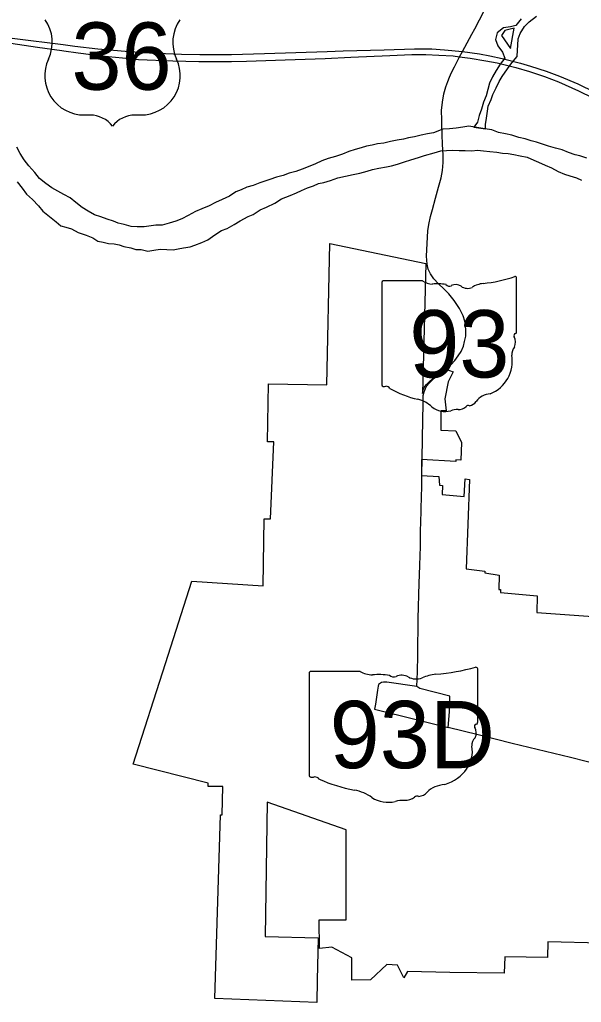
# Model space of a CAD drawing. Extents: x -6.3 to 34, y 0 to 22.
# Drawn here: x 10.181 to 10.934, y 11.977 to 13.296 of the extents above; entities that cross this region are included whole.
import ezdxf

# ---------------------------------------------------------------- set-up
doc = ezdxf.new("R2010")
doc.units = 0
for name, color, linetype in [('GM_X_Corporation', 7, 'Continuous'), ('GM_X_Major_River', 7, 'Continuous'), ('GM_X_Minor_Lake', 7, 'Continuous'), ('GM_X_Minor_River', 7, 'Continuous'), ('GM_X_State_Route', 7, 'Continuous'), ('GM_X_State_Shield', 7, 'Continuous'), ('GM_X_US_Location', 7, 'Continuous'), ('GM_X_US_Route', 7, 'Continuous'), ('GM_X_US_Shield', 7, 'Continuous')]:
    doc.layers.add(name, color=color, linetype=linetype)

msp = doc.modelspace()

# ---------------------------------------------------------------- linework, layer by layer
at = {"layer": 'GM_X_Corporation'}
msp.add_lwpolyline([(10.9606, 12.0567), (10.8895, 12.0582), (10.8889, 12.0373), (10.8316, 12.0383), (10.8309, 12.0164), (10.7579, 12.0172), (10.701, 12.0184), (10.6963, 12.0101), (10.6876, 12.027), (10.6736, 12.0277), (10.6514, 12.0072), (10.6264, 12.0066), (10.6265, 12.037), (10.5999, 12.0509), (10.583, 12.0495), (10.5828, 12.0879), (10.6188, 12.0879), (10.6188, 12.2086), (10.513, 12.2458), (10.5105, 12.0653), (10.5814, 12.0637), (10.5799, 12.0069), (10.5797, 11.977), (10.443, 11.9822), (10.4504, 12.229), (10.4526, 12.229), (10.4537, 12.2668), (10.434, 12.267), (10.4339, 12.2715), (10.3335, 12.2968), (10.3766, 12.4319), (10.4119, 12.5427), (10.5077, 12.5364), (10.5088, 12.6263), (10.5174, 12.6261), (10.5218, 12.7297), (10.5134, 12.7294), (10.5148, 12.8073), (10.5931, 12.806), (10.5968, 12.9958), (10.7256, 12.9689), (10.7211, 12.7944), (10.7221, 12.7993), (10.7234, 12.8023), (10.7265, 12.8066), (10.7306, 12.8107), (10.7385, 12.8171), (10.7526, 12.8273), (10.7626, 12.8235), (10.7557, 12.8103), (10.7514, 12.7875), (10.7532, 12.7711), (10.7459, 12.7714), (10.7459, 12.7454), (10.7662, 12.7442), (10.7734, 12.7285), (10.7727, 12.7049), (10.7661, 12.7053), (10.766, 12.7032), (10.7201, 12.7059), (10.7201, 12.6842), (10.7434, 12.6832), (10.7443, 12.6713), (10.7481, 12.671), (10.7478, 12.659), (10.777, 12.6561), (10.7783, 12.6798), (10.7844, 12.6789), (10.7798, 12.5591), (10.8049, 12.556), (10.8049, 12.5539), (10.8241, 12.5507), (10.8237, 12.5312), (10.8258, 12.5311), (10.8258, 12.5273), (10.8751, 12.5227), (10.8744, 12.5005), (10.9685, 12.4936)], dxfattribs=at)
at = {"layer": 'GM_X_Major_River'}
msp.add_line((10.8049, 13.1499), (10.7834, 13.1533), dxfattribs=at)
for points in [[(10.7485, 13.1492), (10.7361, 13.1446), (10.7278, 13.1433), (10.7195, 13.1414), (10.7107, 13.139), (10.7024, 13.1377), (10.6957, 13.1358), (10.6874, 13.1344), (10.6784, 13.1326), (10.6696, 13.1307), (10.6608, 13.1296), (10.654, 13.128), (10.646, 13.1264), (10.639, 13.1245), (10.631, 13.1219), (10.6225, 13.1192), (10.6139, 13.116), (10.6044, 13.1126), (10.595, 13.1099), (10.5865, 13.1067), (10.5777, 13.1028), (10.5679, 13.0988), (10.5601, 13.0957), (10.5516, 13.0927), (10.5426, 13.0903), (10.5343, 13.0872), (10.5255, 13.085), (10.5167, 13.0816), (10.51, 13.0797), (10.5032, 13.0771), (10.4942, 13.0737), (10.4857, 13.0713), (10.4782, 13.0681), (10.4709, 13.0652), (10.4624, 13.0594), (10.4526, 13.0547), (10.4438, 13.051), (10.435, 13.0465), (10.4255, 13.0423), (10.4167, 13.0388), (10.4071, 13.0336), (10.3986, 13.0291), (10.3906, 13.0259), (10.3815, 13.023), (10.3722, 13.0206), (10.3639, 13.0203), (10.3572, 13.0195), (10.3481, 13.0181), (10.3388, 13.0183), (10.3305, 13.0188), (10.3214, 13.0213), (10.3133, 13.0233), (10.3068, 13.0259), (10.2983, 13.0287), (10.2897, 13.0318), (10.2814, 13.0343), (10.2731, 13.0394), (10.2647, 13.0443), (10.2564, 13.0508), (10.2486, 13.057), (10.2403, 13.0616), (10.2322, 13.0662), (10.2244, 13.0706), (10.2163, 13.0765), (10.2077, 13.0829), (10.2012, 13.0912), (10.1934, 13.1), (10.1871, 13.108), (10.1816, 13.1168), (10.1771, 13.1254)], [(10.7834, 13.1533), (10.7753, 13.1521), (10.7663, 13.1507), (10.7575, 13.1499), (10.7485, 13.1492)], [(10.9416, 13.1104), (10.9325, 13.1134), (10.926, 13.1149), (10.9171, 13.1182), (10.9085, 13.1215), (10.8997, 13.124), (10.8904, 13.1265), (10.882, 13.129), (10.874, 13.1317), (10.8672, 13.1337), (10.8589, 13.1362), (10.8506, 13.1382), (10.8412, 13.1412), (10.8327, 13.1432), (10.8231, 13.1449), (10.8142, 13.1484), (10.8049, 13.1499)], [(10.618, 13.0864), (10.6281, 13.0886), (10.6372, 13.0902), (10.647, 13.0929), (10.6542, 13.095), (10.6628, 13.0971), (10.6729, 13.0987), (10.6799, 13.1001), (10.6876, 13.1022), (10.6972, 13.1057), (10.7055, 13.1083), (10.7158, 13.1115), (10.7241, 13.1139), (10.737, 13.1176), (10.7461, 13.1203)], [(10.7461, 13.1203), (10.7609, 13.1213), (10.7703, 13.1209), (10.7786, 13.1207), (10.7874, 13.1203), (10.7951, 13.1212), (10.8029, 13.1202), (10.8117, 13.1193), (10.8208, 13.1184), (10.8286, 13.1172), (10.8361, 13.1167), (10.8439, 13.1153), (10.8522, 13.1135), (10.8618, 13.1116), (10.8704, 13.1078), (10.8769, 13.105), (10.8857, 13.1009), (10.8941, 13.0974), (10.9032, 13.0926), (10.9118, 13.089), (10.9188, 13.0868), (10.9279, 13.0838), (10.9347, 13.0807)], [(10.1779, 13.0786), (10.1842, 13.0701), (10.1902, 13.0623), (10.1983, 13.0548), (10.2064, 13.0465), (10.2122, 13.0393), (10.2299, 13.0249), (10.2364, 13.0197), (10.2431, 13.0179), (10.2504, 13.0154), (10.2593, 13.0108), (10.2702, 13.0069), (10.279, 13.0034), (10.286, 12.999), (10.293, 12.9975), (10.3, 12.9957), (10.3076, 12.9952), (10.3143, 12.9942), (10.3208, 12.9919), (10.3301, 12.9899), (10.3369, 12.9879), (10.3439, 12.9877), (10.353, 12.9857), (10.361, 12.9868), (10.3696, 12.9881), (10.3786, 12.9876), (10.3867, 12.9874), (10.3937, 12.9888), (10.4006, 12.9899), (10.4095, 12.9915), (10.4162, 12.9934), (10.4255, 12.9971), (10.4332, 13.0007), (10.4428, 13.0073), (10.4516, 13.0131), (10.4593, 13.016), (10.4689, 13.0215), (10.4769, 13.0262), (10.4877, 13.032), (10.4944, 13.0349), (10.5037, 13.041), (10.5123, 13.0447), (10.5231, 13.0502), (10.5324, 13.056), (10.5438, 13.0605), (10.5521, 13.0639), (10.559, 13.0668), (10.567, 13.0708), (10.5751, 13.0734), (10.582, 13.0766), (10.5888, 13.0777), (10.5981, 13.0806), (10.6079, 13.084), (10.618, 13.0864)]]:
    msp.add_lwpolyline(points, dxfattribs=at)
at = {"layer": 'GM_X_Minor_Lake'}
for points in [[(10.8318, 13.2817), (10.8272, 13.2751), (10.8395, 13.2578)], [(10.8395, 13.2578), (10.8442, 13.2849), (10.8318, 13.2817)]]:
    msp.add_lwpolyline(points, dxfattribs=at)
at = {"layer": 'GM_X_Minor_River'}
msp.add_line((10.7901, 13.1522), (10.8057, 13.1498), dxfattribs=at)
for points in [[(10.8057, 13.1498), (10.8057, 13.1556), (10.8071, 13.1642), (10.8083, 13.1736), (10.8095, 13.1801), (10.8133, 13.1893), (10.8158, 13.196), (10.8199, 13.2049), (10.8239, 13.2135), (10.828, 13.2201), (10.8351, 13.2303), (10.8413, 13.2382), (10.8484, 13.2471), (10.8488, 13.2554), (10.849, 13.2619), (10.8497, 13.2708), (10.8522, 13.2778), (10.8583, 13.287), (10.8645, 13.2936), (10.874, 13.3012)], [(10.8535, 13.2976), (10.8464, 13.2887), (10.8391, 13.2868), (10.8298, 13.2854), (10.8216, 13.2788), (10.8191, 13.2699), (10.8221, 13.2614), (10.8286, 13.2529), (10.8318, 13.2448), (10.8255, 13.2367), (10.8199, 13.2283), (10.815, 13.2197), (10.8112, 13.2113), (10.8087, 13.2025), (10.8068, 13.1941), (10.8032, 13.1858), (10.8002, 13.1764), (10.7975, 13.1675), (10.795, 13.1589), (10.7901, 13.1522)]]:
    msp.add_lwpolyline(points, dxfattribs=at)
at = {"layer": 'GM_X_State_Route'}
for p, q in [((10.7843, 13.2712), (10.7874, 13.277)), ((10.7203, 12.6857), (10.7207, 12.7061))]:
    msp.add_line(p, q, dxfattribs=at)
for points in [[(10.7874, 13.277), (10.7915, 13.2842), (10.8041, 13.3082)], [(10.7711, 13.2465), (10.7751, 13.2537), (10.7843, 13.2712)], [(10.7472, 13.1558), (10.747, 13.162), (10.7468, 13.1745), (10.748, 13.1854), (10.75, 13.1968), (10.7524, 13.206), (10.7551, 13.2133), (10.7575, 13.2192), (10.7603, 13.2255), (10.7643, 13.2332), (10.7711, 13.2465)], [(10.7442, 12.8205), (10.7521, 12.8267), (10.7598, 12.8336), (10.7646, 12.8388), (10.7692, 12.8449), (10.7731, 12.8507), (10.7763, 12.8582), (10.7778, 12.8641), (10.7792, 12.8713), (10.7792, 12.8787), (10.7791, 12.8861), (10.778, 12.8915), (10.7758, 12.8987), (10.771, 12.9085), (10.7638, 12.9191), (10.7565, 12.9282), (10.7497, 12.9351), (10.7429, 12.9419), (10.7363, 12.9486), (10.7321, 12.9553), (10.7291, 12.9616), (10.7276, 12.9679), (10.7268, 12.9788), (10.7278, 13.0043), (10.7286, 13.013), (10.7299, 13.0215), (10.7319, 13.0319), (10.7345, 13.0416), (10.7389, 13.0569), (10.7427, 13.0714), (10.7463, 13.0842), (10.7481, 13.0937), (10.7491, 13.1045), (10.749, 13.1148), (10.7483, 13.1286), (10.7476, 13.1422), (10.7472, 13.1558)], [(10.722, 12.7814), (10.7221, 12.7862), (10.7224, 12.7917), (10.7234, 12.7965), (10.7251, 12.801), (10.7269, 12.8046), (10.7301, 12.8085), (10.7341, 12.8123), (10.7385, 12.816), (10.7442, 12.8205)], [(10.7207, 12.7061), (10.7213, 12.7347), (10.722, 12.7814)], [(10.7173, 12.5509), (10.7177, 12.5642), (10.7184, 12.5889), (10.7188, 12.6092), (10.7193, 12.6361), (10.7199, 12.6593), (10.7202, 12.6655), (10.7203, 12.6837), (10.7203, 12.6857)], [(10.7138, 12.4013), (10.7146, 12.4207), (10.7152, 12.4431), (10.7154, 12.4922), (10.717, 12.5397), (10.7173, 12.5509)], [(10.6661, 12.4066), (10.6624, 12.4039), (10.6618, 12.4014), (10.6611, 12.3962), (10.6583, 12.3774), (10.6567, 12.3708)], [(10.7138, 12.4013), (10.6733, 12.4068), (10.669, 12.407), (10.6661, 12.4066)], [(10.7581, 12.3881), (10.7179, 12.3984), (10.7138, 12.4013)], [(10.7559, 12.3462), (10.7574, 12.3669), (10.7581, 12.3881)], [(10.6567, 12.3708), (10.7128, 12.3568), (10.7559, 12.3462)], [(10.9667, 12.2938), (10.9619, 12.2948), (10.9199, 12.3056), (10.8417, 12.3246), (10.7958, 12.3362), (10.7559, 12.3462)]]:
    msp.add_lwpolyline(points, dxfattribs=at)
at = {"layer": 'GM_X_State_Shield'}
for p, q in [((10.6668, 12.9434), (10.6668, 12.8063)), ((10.7214, 12.9458), (10.6685, 12.9458)), ((10.8475, 12.8775), (10.8475, 12.9492)), ((10.8474, 12.8775), (10.8475, 12.8775)), ((10.5694, 12.4189), (10.5694, 12.2817)), ((10.6378, 12.4212), (10.5717, 12.4212)), ((10.7953, 12.3529), (10.7953, 12.4246)), ((10.7953, 12.3529), (10.7953, 12.3529))]:
    msp.add_line(p, q, dxfattribs=at)
for centre, radius, start, end in [((10.6688, 12.9437), 0.00209, 98.1301, 188.1301), ((10.7341, 12.9617), 0.0203, 231.6195, 271.1119), ((10.7831, 13.1328), 0.1916, 275.8445, 288.9065), ((10.8454, 12.9495), 0.00201, 351.8621, 97.738), ((10.7408, 12.8688), 0.0729, 80.4867, 94.9883), ((10.7573, 12.9444), 0.00586, 219.7921, 297.1024), ((10.7659, 12.9286), 0.0122, 54.4667, 119.1411), ((10.7817, 12.9503), 0.0147, 233.8562, 294.8282), ((10.8075, 12.9039), 0.0386, 97.3462, 120.7689), ((10.8453, 12.8772), 0.00215, 289.6038, 7.7341), ((10.847, 12.8722), 0.00311, 107.944, 210.337), ((10.8272, 12.8631), 0.0187, 340.033, 23.6496), ((10.8547, 12.8474), 0.0136, 136.8065, 186.9296), ((10.7938, 12.8383), 0.0479, 292.3089, 8.9858), ((10.6688, 12.806), 0.00211, 171.9584, 258.3066), ((10.6692, 12.82), 0.0161, 267.339, 280.6039), ((10.6725, 12.7984), 0.00581, 29.7484, 93.2717), ((10.7458, 12.9216), 0.1384, 240.4129, 257.1985), ((10.7046, 12.7447), 0.0433, 47.1842, 75.836), ((10.814, 12.7678), 0.0263, 94.4031, 142.5768), ((10.7514, 12.7977), 0.0275, 230.7004, 286.2918), ((10.7673, 12.7503), 0.0226, 85.6951, 111.2099), ((10.7693, 12.7874), 0.0146, 268.777, 315.5493), ((10.7825, 12.7741), 0.00412, 65.7517, 132.6484), ((10.7808, 12.793), 0.0155, 282.8732, 323.2771)]:
    msp.add_arc(centre, radius, start, end, dxfattribs=at)
for centre, major_axis, start_param, end_param in [((10.572, 12.4192), (0.00262, 0), 1.712693, 3.28349), ((10.6536, 12.4372), (0.0254, 0), 4.042523, 4.731795), ((10.662, 12.3442), (0.0911, 0), 1.404758, 1.657858), ((10.6827, 12.4199), (0.00732, 0), 3.836095, 5.185415), ((10.6934, 12.404), (0.0152, 0), 0.950623, 2.079405), ((10.7454, 12.3794), (0.0482, 0), 1.699011, 2.107814), ((10.7149, 12.6082), (0.2395, 0), 4.814394, 5.042369), ((10.7928, 12.4249), (0.00251, 0), 6.141152, 7.989035), ((10.7131, 12.4258), (0.0183, 0), 4.081561, 5.145723), ((10.7947, 12.3476), (0.00389, 0), 1.883978, 3.671073), ((10.7926, 12.3526), (0.00269, 0), 5.05454, 6.418171), ((10.77, 12.3386), (0.0234, 0), 5.934695, 6.695948), ((10.8043, 12.3229), (0.017, 0), 2.387724, 3.262537), ((10.7283, 12.3137), (0.0599, 0), 5.101752, 6.440018), ((10.572, 12.2814), (0.00264, 0), 3.00124, 4.508301), ((10.5724, 12.2955), (0.0201, 0), 4.665946, 4.897461), ((10.5766, 12.2738), (0.00726, 0), 0.519207, 1.627899), ((10.6683, 12.397), (0.173, 0), 4.195997, 4.488961), ((10.6167, 12.2201), (0.0541, 0), 0.823519, 1.323587), ((10.712, 12.2684), (0.0194, 0), 4.937069, 5.64225), ((10.7535, 12.2432), (0.0328, 0), 1.647645, 2.488434), ((10.6752, 12.2731), (0.0343, 0), 4.026481, 4.996735), ((10.6951, 12.2257), (0.0282, 0), 1.495662, 1.94098), ((10.6976, 12.2629), (0.0183, 0), 4.691044, 5.507374), ((10.7142, 12.2496), (0.00515, 0), 1.147584, 2.315152)]:
    msp.add_ellipse(centre, major_axis=major_axis, ratio=0.8, start_param=start_param, end_param=end_param, dxfattribs=at)
at = {"layer": 'GM_X_US_Route'}
for points in [[(9.754, 13.2178), (9.7585, 13.2196), (9.8018, 13.2362), (9.8617, 13.2596), (9.9017, 13.2745), (9.9199, 13.28), (9.9371, 13.2841), (9.9529, 13.2871), (9.976, 13.2898), (9.9914, 13.2908), (10.0059, 13.2905), (10.0218, 13.29), (10.039, 13.2887), (10.1438, 13.2751), (10.1748, 13.2709), (10.2394, 13.2628)], [(9.7534, 13.2099), (9.7585, 13.212), (9.8545, 13.2511), (9.8929, 13.266), (9.9138, 13.2731), (9.9196, 13.2745), (9.9414, 13.28), (9.9577, 13.2827), (9.9712, 13.2844), (9.9865, 13.2855), (10.005, 13.2856), (10.0231, 13.285), (10.0441, 13.283), (10.0825, 13.2779), (10.2051, 13.2594), (10.2376, 13.2548)], [(10.2394, 13.2628), (10.255, 13.2608), (10.2861, 13.2572), (10.3224, 13.2541), (10.355, 13.2519), (10.3982, 13.2502), (10.4229, 13.2496), (10.4651, 13.2496), (10.5095, 13.251), (10.5933, 13.2538), (10.615, 13.2545), (10.6699, 13.256), (10.7107, 13.2572), (10.734, 13.2571), (10.7506, 13.2559), (10.7751, 13.2537), (10.7979, 13.2504), (10.8117, 13.248), (10.8283, 13.2441), (10.8528, 13.2379), (10.8662, 13.2338), (10.8871, 13.2271), (10.9052, 13.2204), (10.9295, 13.21), (10.9524, 13.1989)], [(10.2376, 13.2548), (10.2403, 13.2544), (10.2596, 13.2517), (10.2906, 13.2478), (10.319, 13.2449), (10.3406, 13.2431), (10.3864, 13.241), (10.4215, 13.2402), (10.4482, 13.2401), (10.4651, 13.2402), (10.4851, 13.2407), (10.5373, 13.2423), (10.5907, 13.2441), (10.6254, 13.2458), (10.6777, 13.2483), (10.7071, 13.2495), (10.7256, 13.2496), (10.7431, 13.2489), (10.7622, 13.2477), (10.7711, 13.2465)], [(10.7711, 13.2465), (10.7853, 13.2447), (10.8061, 13.2413), (10.8213, 13.2383), (10.8464, 13.2322), (10.8649, 13.2269), (10.885, 13.22), (10.9037, 13.213), (10.9307, 13.201), (10.9497, 13.1913)]]:
    msp.add_lwpolyline(points, dxfattribs=at)
at = {"layer": 'GM_X_US_Shield'}
for p, q in [((10.268, 13.1684), (10.2755, 13.1684)), ((10.3357, 13.1684), (10.3433, 13.1684))]:
    msp.add_line(p, q, dxfattribs=at)
for centre, radius, start, end in [((10.1721, 13.2661), 0.0527, 334.5471, 35.0009), ((10.4391, 13.2661), 0.0527, 144.9991, 205.4529), ((10.2674, 13.2211), 0.0527, 154.8319, 270.6383), ((10.3438, 13.2211), 0.0527, 269.3617, 25.1681), ((10.2755, 13.1307), 0.0376, 36.8699, 90), ((10.3357, 13.1307), 0.0376, 90, 143.1301)]:
    msp.add_arc(centre, radius, start, end, dxfattribs=at)

# ---------------------------------------------------------------- texts
at = {"layer": 'GM_X_State_Shield'}
for s, p in [('93', (10.7035, 12.816)), ('93D', (10.5968, 12.2914))]:
    msp.add_text(s, height=0.09035, dxfattribs=at).set_placement(p)
at = {"layer": 'GM_X_US_Location'}
for s in ['0', '/']:
    msp.add_text(s, height=0.00013, dxfattribs=at).set_placement((10.3056, 13.2467))
msp.add_text('36', height=0.00013, rotation=0, dxfattribs=at).set_placement((10.2788, 13.2199))
at = {"layer": 'GM_X_US_Shield'}
msp.add_text('36', height=0.09035, dxfattribs=at).set_placement((10.2505, 13.2023))

doc.saveas('drawing.dxf')
